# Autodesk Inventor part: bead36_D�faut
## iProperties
Created: 2011-01
Part Number: bead36_D�faut
Document SubType Name: Modeling
Designer: eric
Density: 1 g/cm^3
Mass: 0.0716274 g
Surface Area: 2.42818 cm^2
Volume: 0.0716274 cm^3
Author: eric
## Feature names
1. Base1
